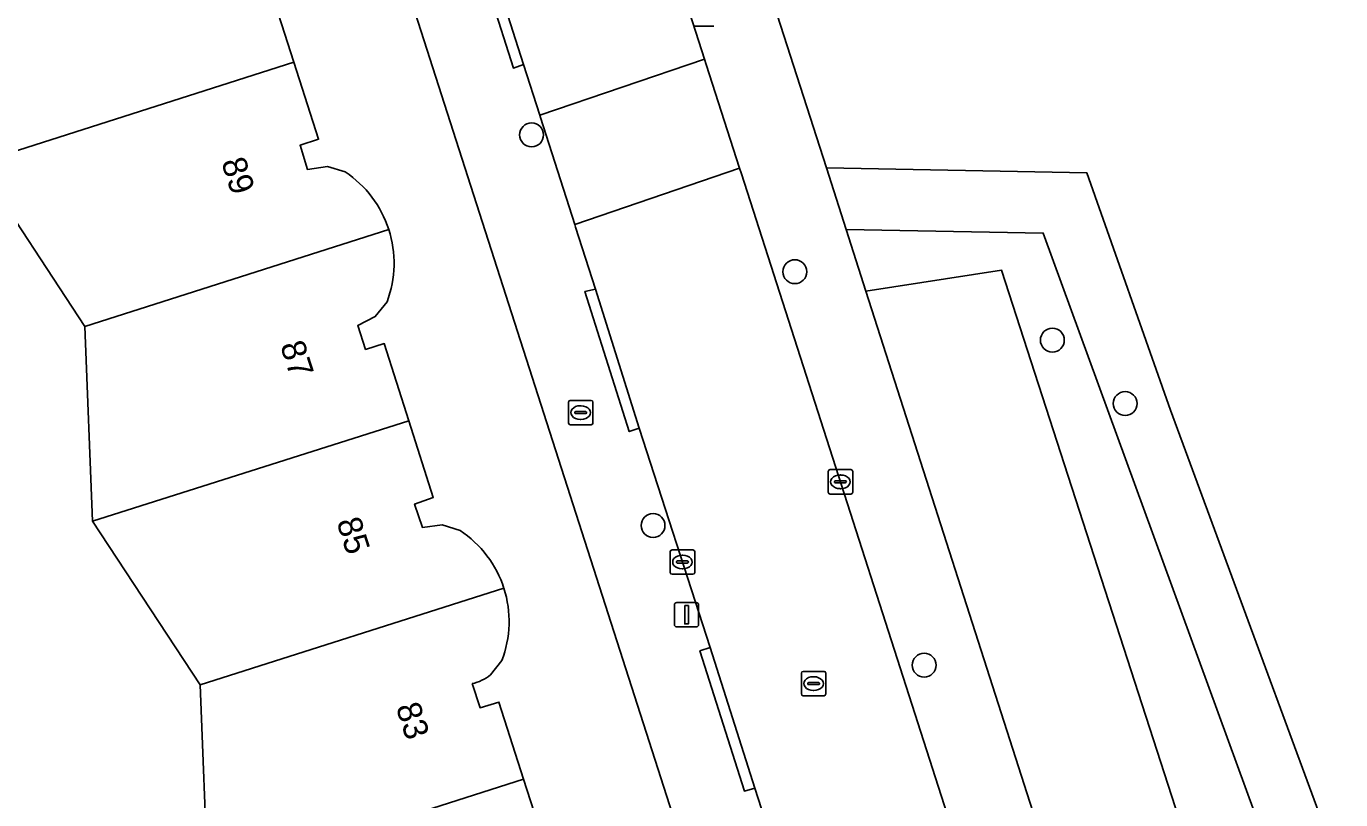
# Model space of a CAD drawing. Extents: x 159499 to 160349, y 382524 to 383273.
# Drawn here: x 159697.8 to 159751.6, y 382873.9 to 382905.5 of the extents above; entities that cross this region are included whole.
import ezdxf

# ---------------------------------------------------------------- set-up
doc = ezdxf.new("R2010")
doc.units = 0
for name, color, linetype in [('IMGEO_Boom', 7, 'Continuous'), ('IMGEO_Brandkraan', 7, 'Continuous'), ('IMGEO_Erf', 7, 'Continuous'), ('IMGEO_Groenvoorziening', 7, 'Continuous'), ('IMGEO_Kolk', 7, 'Continuous'), ('IMGEO_Lichtmast', 7, 'Continuous'), ('IMGEO_Pand', 7, 'Continuous'), ('IMGEO_Pand_nummerreeks', 7, 'Continuous'), ('IMGEO_Rijbaan_lokaal_open', 7, 'Continuous'), ('IMGEO_Rioolput', 7, 'Continuous'), ('IMGEO_Voetpad_open', 7, 'Continuous')]:
    doc.layers.add(name, color=color, linetype=linetype)

msp = doc.modelspace()

# ---------------------------------------------------------------- linework, layer by layer
at = {"layer": 'IMGEO_Boom'}
for centre in [(159718.486, 382901.102), (159729.256, 382895.502), (159739.792, 382892.702), (159742.771, 382890.104), (159723.454, 382885.115), (159734.547, 382879.398)]:
    msp.add_circle(centre, 0.489, dxfattribs=at)
at = {"layer": 'IMGEO_Brandkraan'}
for p, q in [((159720.068, 382890.235), (159720.92, 382890.235)), ((159719.993, 382889.309), (159719.993, 382890.161)), ((159720.252, 382889.729), (159720.252, 382889.741)), ((159720.69, 382889.692), (159720.292, 382889.692)), ((159720.295, 382889.778), (159720.693, 382889.778)), ((159720.481, 382890.015), (159720.506, 382890.015)), ((159720.736, 382889.741), (159720.736, 382889.729)), ((159720.994, 382890.161), (159720.994, 382889.309)), ((159720.92, 382889.235), (159720.068, 382889.235)), ((159720.504, 382889.455), (159720.479, 382889.455))]:
    msp.add_line(p, q, dxfattribs=at)
for points in [[(159720.068, 382890.235), (159720.92, 382890.235)], [(159719.993, 382889.309), (159719.993, 382890.161)], [(159720.994, 382890.161), (159720.994, 382889.309)], [(159720.92, 382889.235), (159720.068, 382889.235)]]:
    msp.add_lwpolyline(points, dxfattribs=at)
for centre, radius, start, end in [((159720.07, 382890.159), 0.0765, 91.552, 178.448), ((159720.07, 382890.159), 0.0765, 91.552, 178.448), ((159720.918, 382890.159), 0.0765, 1.552, 88.448), ((159720.918, 382890.159), 0.0765, 1.552, 88.448), ((159720.292, 382889.738), 0.0403, 85.8775, 175.7526), ((159720.289, 382889.728), 0.0366, 178.938, 274.7102), ((159720.693, 382889.735), 0.043, 264.8664, 352.4533), ((159720.697, 382889.74), 0.0386, 1.7309, 96.639), ((159720.07, 382889.311), 0.0765, 181.552, 268.448), ((159720.07, 382889.311), 0.0765, 181.552, 268.448), ((159720.918, 382889.311), 0.0765, 271.552, 358.448), ((159720.918, 382889.311), 0.0765, 271.552, 358.448)]:
    msp.add_arc(centre, radius, start, end, dxfattribs=at)
for centre, major_axis, ratio, start_param, end_param in [((159720.48, 382889.735), (-0.387, 0.002), 0.722429, 4.712389, 7.853982), ((159720.505, 382889.735), (-0.39, 0.002), 0.717154, 1.570796, 4.712389)]:
    msp.add_ellipse(centre, major_axis=major_axis, ratio=ratio, start_param=start_param, end_param=end_param, dxfattribs=at)
at = {"layer": 'IMGEO_Erf'}
for points in [[(159797.571, 382912.547), (159772.924, 382944.336), (159765.561, 382953.83), (159760.969, 382951.204), (159750.017, 382945.267), (159739.773, 382940.307), (159729.278, 382935.832), (159728.417, 382938.099), (159719.333, 382934.542), (159720.458, 382931.079), (159730.546, 382899.75), (159741.202, 382899.547), (159744.626, 382889.831), (159753.21, 382866.555), (159754.229, 382863.79), (159753.482, 382863.418), (159757.881, 382849.879), (159758.599, 382850.174), (159770.661, 382815.939), (159788.308, 382822.433), (159800.223, 382826.817), (159778.58, 382886.258)], [(159726.407, 382866.582), (159705.82, 382930.705)], [(159705.241, 382870.601), (159704.925, 382878.587), (159700.522, 382885.291), (159700.207, 382893.265), (159695.816, 382899.951), (159695.66, 382903.906), (159695.441, 382903.898), (159695.397, 382904.99), (159695.61, 382904.992), (159695.502, 382907.919), (159693.888, 382910.368), (159693.704, 382910.247), (159693.109, 382911.146), (159693.293, 382911.268), (159691.092, 382914.595), (159690.949, 382918.555), (159690.729, 382918.547), (159690.691, 382919.636), (159690.915, 382919.634), (159690.817, 382922.747), (159689.861, 382925.725), (159681.49, 382922.46)], [(159707.857, 382908.933), (159707.38, 382908.35), (159706.66, 382907.98), (159706.973, 382906.993), (159707.752, 382907.236), (159708.761, 382904.08), (159709.772, 382900.92), (159709.011, 382900.677), (159709.32, 382899.685), (159710.133, 382899.802), (159710.86, 382899.584)], [(159712.571, 382894.273), (159712.088, 382893.664), (159711.369, 382893.301), (159711.693, 382892.321), (159712.458, 382892.561), (159713.463, 382889.399), (159714.461, 382886.256), (159713.7, 382885.991), (159714.025, 382885.03), (159714.827, 382885.14), (159715.558, 382884.907)], [(159717.266, 382879.584), (159716.804, 382879.003)], [(159716.052, 382878.641), (159716.38, 382877.657), (159717.146, 382877.885), (159718.157, 382874.729), (159719.171, 382871.564), (159718.394, 382871.332), (159718.71, 382870.347), (159719.467, 382870.509)]]:
    msp.add_lwpolyline(points, dxfattribs=at)
for centre, radius, start, end in [((159708.371, 382895.852), 4.486, 17.9077, 56.3059), ((159708.365, 382895.851), 4.493, 339.4374, 17.8901), ((159713.116, 382881.188), 4.449, 17.7159, 56.7108), ((159713.114, 382881.188), 4.451, 338.8806, 17.7113), ((159715.685, 382880.366), 1.763, 282.0162, 309.3945)]:
    msp.add_arc(centre, radius, start, end, dxfattribs=at)
at = {"layer": 'IMGEO_Groenvoorziening'}
msp.add_lwpolyline([(159802.405, 382822.292), (159800.752, 382827.014), (159800.223, 382826.817), (159788.308, 382822.433), (159788.827, 382821.022), (159771.392, 382812.521), (159757.881, 382849.879), (159753.482, 382863.418), (159754.229, 382863.79), (159753.21, 382866.555), (159744.626, 382889.831), (159741.202, 382899.547), (159730.546, 382899.75), (159731.353, 382897.234), (159739.421, 382897.08), (159751.108, 382865.029), (159750.438, 382864.695), (159756.337, 382846.542), (159757.115, 382846.862), (159769.976, 382810.359)], close=True, dxfattribs=at)
for points in [[(159803.042, 382820.472), (159802.405, 382822.292), (159769.976, 382810.359), (159757.115, 382846.862), (159756.337, 382846.542), (159750.438, 382864.695), (159751.108, 382865.029), (159739.421, 382897.08), (159731.353, 382897.234), (159732.164, 382894.706), (159737.708, 382895.57), (159759.661, 382827.691), (159765.488, 382806.454), (159767.125, 382805.829), (159767.559, 382806.835), (159774.261, 382804.239), (159773.875, 382803.253), (159775.647, 382802.577)], [(159765.488, 382806.454), (159759.661, 382827.691), (159737.708, 382895.57), (159732.164, 382894.706)], [(159732.164, 382894.706), (159759.612, 382809.126)]]:
    msp.add_lwpolyline(points, dxfattribs=at)
at = {"layer": 'IMGEO_Kolk'}
for p, q in [((159730.621, 382886.475), (159730.621, 382887.327)), ((159730.696, 382887.401), (159731.548, 382887.401)), ((159731.109, 382887.181), (159731.134, 382887.181)), ((159731.622, 382887.327), (159731.622, 382886.475)), ((159730.88, 382886.895), (159730.88, 382886.907)), ((159731.318, 382886.858), (159730.92, 382886.858)), ((159730.923, 382886.944), (159731.321, 382886.944)), ((159731.132, 382886.621), (159731.107, 382886.621)), ((159731.364, 382886.907), (159731.364, 382886.895)), ((159731.548, 382886.401), (159730.696, 382886.401)), ((159724.157, 382883.192), (159724.157, 382884.044)), ((159724.232, 382884.118), (159725.084, 382884.118)), ((159724.645, 382883.898), (159724.67, 382883.898)), ((159725.158, 382884.044), (159725.158, 382883.192)), ((159724.416, 382883.612), (159724.416, 382883.624)), ((159724.854, 382883.575), (159724.456, 382883.575)), ((159724.459, 382883.661), (159724.857, 382883.661)), ((159724.668, 382883.338), (159724.643, 382883.338)), ((159724.9, 382883.624), (159724.9, 382883.612)), ((159725.084, 382883.118), (159724.232, 382883.118))]:
    msp.add_line(p, q, dxfattribs=at)
for points in [[(159730.621, 382886.475), (159730.621, 382887.327)], [(159730.696, 382887.401), (159731.548, 382887.401)], [(159731.622, 382887.327), (159731.622, 382886.475)], [(159731.548, 382886.401), (159730.696, 382886.401)], [(159724.157, 382883.192), (159724.157, 382884.044)], [(159724.232, 382884.118), (159725.084, 382884.118)], [(159725.158, 382884.044), (159725.158, 382883.192)], [(159725.084, 382883.118), (159724.232, 382883.118)]]:
    msp.add_lwpolyline(points, dxfattribs=at)
for centre, radius, start, end in [((159730.698, 382887.325), 0.0765, 91.552, 178.448), ((159730.698, 382887.325), 0.0765, 91.552, 178.448), ((159731.546, 382887.325), 0.0765, 1.552, 88.448), ((159731.546, 382887.325), 0.0765, 1.552, 88.448), ((159730.698, 382886.477), 0.0765, 181.552, 268.448), ((159730.698, 382886.477), 0.0765, 181.552, 268.448), ((159730.92, 382886.904), 0.0403, 85.8775, 175.7526), ((159730.917, 382886.894), 0.0366, 178.938, 274.7102), ((159731.321, 382886.901), 0.043, 264.8664, 352.4533), ((159731.325, 382886.906), 0.0386, 1.7309, 96.639), ((159731.546, 382886.477), 0.0765, 271.552, 358.448), ((159731.546, 382886.477), 0.0765, 271.552, 358.448), ((159724.234, 382884.042), 0.0765, 91.552, 178.448), ((159724.234, 382884.042), 0.0765, 91.552, 178.448), ((159725.082, 382884.042), 0.0765, 1.552, 88.448), ((159725.082, 382884.042), 0.0765, 1.552, 88.448), ((159724.234, 382883.194), 0.0765, 181.552, 268.448), ((159724.234, 382883.194), 0.0765, 181.552, 268.448), ((159724.456, 382883.621), 0.0403, 85.8775, 175.7526), ((159724.453, 382883.611), 0.0366, 178.938, 274.7102), ((159724.857, 382883.618), 0.043, 264.8664, 352.4533), ((159724.861, 382883.623), 0.0386, 1.7309, 96.639), ((159725.082, 382883.194), 0.0765, 271.552, 358.448), ((159725.082, 382883.194), 0.0765, 271.552, 358.448)]:
    msp.add_arc(centre, radius, start, end, dxfattribs=at)
for centre, major_axis, ratio, start_param, end_param in [((159731.108, 382886.901), (-0.387, 0.002), 0.722429, 4.712389, 7.853982), ((159731.133, 382886.901), (-0.39, 0.002), 0.717154, 1.570796, 4.712389), ((159724.644, 382883.618), (-0.387, 0.002), 0.722429, 4.712389, 7.853982), ((159724.669, 382883.618), (-0.39, 0.002), 0.717154, 1.570796, 4.712389)]:
    msp.add_ellipse(centre, major_axis=major_axis, ratio=ratio, start_param=start_param, end_param=end_param, dxfattribs=at)
at = {"layer": 'IMGEO_Lichtmast'}
for p, q in [((159725.939, 382905.547), (159725.149, 382905.547)), ((159725.149, 382905.547), (159725.939, 382905.547)), ((159724.329, 382881.063), (159724.329, 382881.863)), ((159724.329, 382881.863), (159724.329, 382881.063)), ((159724.429, 382881.963), (159725.219, 382881.963)), ((159725.219, 382881.963), (159724.429, 382881.963)), ((159725.319, 382881.863), (159725.319, 382881.063)), ((159725.319, 382881.063), (159725.319, 382881.863)), ((159725.219, 382880.963), (159724.429, 382880.963)), ((159724.429, 382880.963), (159725.219, 382880.963))]:
    msp.add_line(p, q, dxfattribs=at)
msp.add_lwpolyline([(159724.749, 382881.838), (159724.899, 382881.838), (159724.899, 382881.088), (159724.749, 382881.088), (159724.749, 382881.838)], dxfattribs=at)
for centre, start, end in [((159724.429, 382881.863), 90, 180), ((159724.429, 382881.863), 90, 180), ((159725.219, 382881.863), 0, 90), ((159725.219, 382881.863), 360, 90), ((159724.429, 382881.063), 180, 270), ((159724.429, 382881.063), 180, 270), ((159725.219, 382881.063), 270, 0), ((159725.219, 382881.063), 270, 0)]:
    msp.add_arc(centre, 0.1, start, end, dxfattribs=at)
at = {"layer": 'IMGEO_Pand'}
for points in [[(159707.929, 382911.894), (159695.502, 382907.919), (159695.61, 382904.992), (159695.397, 382904.99), (159695.441, 382903.898), (159695.66, 382903.906), (159695.816, 382899.951), (159708.761, 382904.08), (159707.752, 382907.236), (159706.973, 382906.993), (159706.66, 382907.98), (159707.38, 382908.35), (159707.857, 382908.933)], [(159710.86, 382899.584), (159710.133, 382899.802), (159709.32, 382899.685), (159709.011, 382900.677), (159709.772, 382900.92), (159708.761, 382904.08), (159695.816, 382899.951), (159700.207, 382893.265), (159712.64, 382897.231)], [(159712.64, 382897.231), (159700.207, 382893.265), (159700.522, 382885.291), (159713.463, 382889.399), (159712.458, 382892.561), (159711.693, 382892.321), (159711.369, 382893.301), (159712.088, 382893.664), (159712.571, 382894.273)], [(159715.558, 382884.907), (159714.827, 382885.14), (159714.025, 382885.03), (159713.7, 382885.991), (159714.461, 382886.256), (159713.463, 382889.399), (159700.522, 382885.291), (159704.925, 382878.587), (159717.354, 382882.542)], [(159717.354, 382882.542), (159704.925, 382878.587), (159705.241, 382870.601), (159718.157, 382874.729), (159717.146, 382877.885), (159716.38, 382877.657), (159716.052, 382878.641)], [(159716.804, 382879.003), (159717.266, 382879.584)], [(159719.467, 382870.509), (159718.71, 382870.347), (159718.394, 382871.332), (159719.171, 382871.564), (159718.157, 382874.729), (159705.241, 382870.601), (159706.992, 382867.936), (159709.737, 382863.757), (159713.674, 382865.027), (159714.015, 382864.029), (159714.185, 382864.083), (159719.528, 382865.788), (159720.203, 382865.998)]]:
    msp.add_lwpolyline(points, dxfattribs=at)
for centre, radius, start, end in [((159708.371, 382895.852), 4.486, 17.9077, 56.3059), ((159708.365, 382895.851), 4.493, 339.4374, 17.8901), ((159713.116, 382881.188), 4.449, 17.7159, 56.7108), ((159713.114, 382881.188), 4.451, 338.8806, 17.7113), ((159715.685, 382880.366), 1.763, 282.0162, 309.3945)]:
    msp.add_arc(centre, radius, start, end, dxfattribs=at)
at = {"layer": 'IMGEO_Rijbaan_lokaal_open'}
msp.add_lwpolyline([(159708.676, 382933.54), (159709.177, 382932.011), (159709.693, 382930.436), (159711.615, 382924.477), (159713.429, 382918.737), (159715.951, 382910.926), (159716.328, 382909.718), (159718.16, 382903.979), (159718.821, 382901.909), (159725.562, 382904.205), (159716.376, 382932.797)], dxfattribs=at)
for points in [[(159720.253, 382897.428), (159726.994, 382899.746), (159725.632, 382903.985), (159725.562, 382904.205), (159718.821, 382901.909), (159718.854, 382901.808)], [(159737.432, 382843.824), (159744.243, 382846.026), (159744.191, 382846.188), (159737.539, 382866.925), (159727.07, 382899.511), (159726.994, 382899.746), (159720.253, 382897.428), (159720.284, 382897.331), (159721.097, 382894.788), (159722.888, 382889.098), (159725.791, 382880.115), (159727.623, 382874.357), (159730.279, 382866.12), (159733.33, 382856.538), (159733.407, 382856.312), (159735.46, 382849.969), (159737.305, 382844.219)]]:
    msp.add_lwpolyline(points, close=True, dxfattribs=at)
at = {"layer": 'IMGEO_Rioolput'}
for p, q in [((159729.522, 382878.218), (159729.522, 382879.07)), ((159729.597, 382879.144), (159730.449, 382879.144)), ((159730.01, 382878.924), (159730.035, 382878.924)), ((159730.523, 382879.07), (159730.523, 382878.218)), ((159729.781, 382878.638), (159729.781, 382878.65)), ((159730.219, 382878.601), (159729.821, 382878.601)), ((159729.824, 382878.687), (159730.222, 382878.687)), ((159730.033, 382878.364), (159730.008, 382878.364)), ((159730.265, 382878.65), (159730.265, 382878.638)), ((159730.449, 382878.144), (159729.597, 382878.144))]:
    msp.add_line(p, q, dxfattribs=at)
for points in [[(159729.522, 382878.218), (159729.522, 382879.07)], [(159729.597, 382879.144), (159730.449, 382879.144)], [(159730.523, 382879.07), (159730.523, 382878.218)], [(159730.449, 382878.144), (159729.597, 382878.144)]]:
    msp.add_lwpolyline(points, dxfattribs=at)
for centre, radius, start, end in [((159729.599, 382879.068), 0.0765, 91.552, 178.448), ((159729.599, 382879.068), 0.0765, 91.552, 178.448), ((159730.447, 382879.068), 0.0765, 1.552, 88.448), ((159730.447, 382879.068), 0.0765, 1.552, 88.448), ((159729.821, 382878.647), 0.0403, 85.8775, 175.7526), ((159729.818, 382878.637), 0.0366, 178.938, 274.7102), ((159730.222, 382878.644), 0.043, 264.8664, 352.4533), ((159730.226, 382878.649), 0.0386, 1.7309, 96.639), ((159729.599, 382878.22), 0.0765, 181.552, 268.448), ((159729.599, 382878.22), 0.0765, 181.552, 268.448), ((159730.447, 382878.22), 0.0765, 271.552, 358.448), ((159730.447, 382878.22), 0.0765, 271.552, 358.448)]:
    msp.add_arc(centre, radius, start, end, dxfattribs=at)
for centre, major_axis, ratio, start_param, end_param in [((159730.009, 382878.644), (-0.387, 0.002), 0.722429, 4.712389, 7.853982), ((159730.034, 382878.644), (-0.39, 0.002), 0.717154, 1.570796, 4.712389)]:
    msp.add_ellipse(centre, major_axis=major_axis, ratio=ratio, start_param=start_param, end_param=end_param, dxfattribs=at)
at = {"layer": 'IMGEO_Voetpad_open'}
for points in [[(159732.164, 382894.706), (159731.353, 382897.234), (159730.546, 382899.75), (159720.458, 382931.079), (159719.333, 382934.542), (159716.054, 382933.725), (159716.376, 382932.797), (159725.562, 382904.205), (159725.632, 382903.985), (159726.994, 382899.746), (159727.07, 382899.511), (159737.539, 382866.925), (159744.191, 382846.188), (159744.243, 382846.026), (159745.318, 382842.675), (159745.694, 382841.502), (159751.166, 382824.443), (159759.246, 382799.219), (159765.262, 382780.583)], [(159705.82, 382930.705), (159726.407, 382866.582)], [(159730.279, 382866.12), (159727.623, 382874.357), (159727.194, 382874.24), (159725.374, 382879.977), (159725.791, 382880.115), (159722.888, 382889.098), (159722.482, 382888.961), (159720.664, 382894.696), (159721.097, 382894.788), (159720.284, 382897.331), (159720.253, 382897.428), (159718.854, 382901.808), (159718.821, 382901.909), (159718.16, 382903.979), (159717.74, 382903.838), (159715.911, 382909.577)], [(159769.997, 382776.771), (159765.523, 382790.674), (159760.683, 382805.736), (159760.145, 382807.41), (159759.612, 382809.126), (159732.164, 382894.706)]]:
    msp.add_lwpolyline(points, dxfattribs=at)
for points in [[(159716.328, 382909.718), (159715.911, 382909.577), (159717.74, 382903.838), (159718.16, 382903.979)], [(159722.888, 382889.098), (159721.097, 382894.788), (159720.664, 382894.696), (159722.482, 382888.961)], [(159727.623, 382874.357), (159725.791, 382880.115), (159725.374, 382879.977), (159727.194, 382874.24)]]:
    msp.add_lwpolyline(points, close=True, dxfattribs=at)

# ---------------------------------------------------------------- texts
at = {"layer": 'IMGEO_Pand_nummerreeks'}
for s, p in [('89', (159705.779, 382899.998)), ('87', (159708.188, 382892.494)), ('85', (159710.495, 382885.269)), ('83', (159712.922, 382877.688))]:
    msp.add_text(s, height=1, rotation=287.7795, dxfattribs=at).set_placement(p)

doc.saveas('drawing.dxf')
